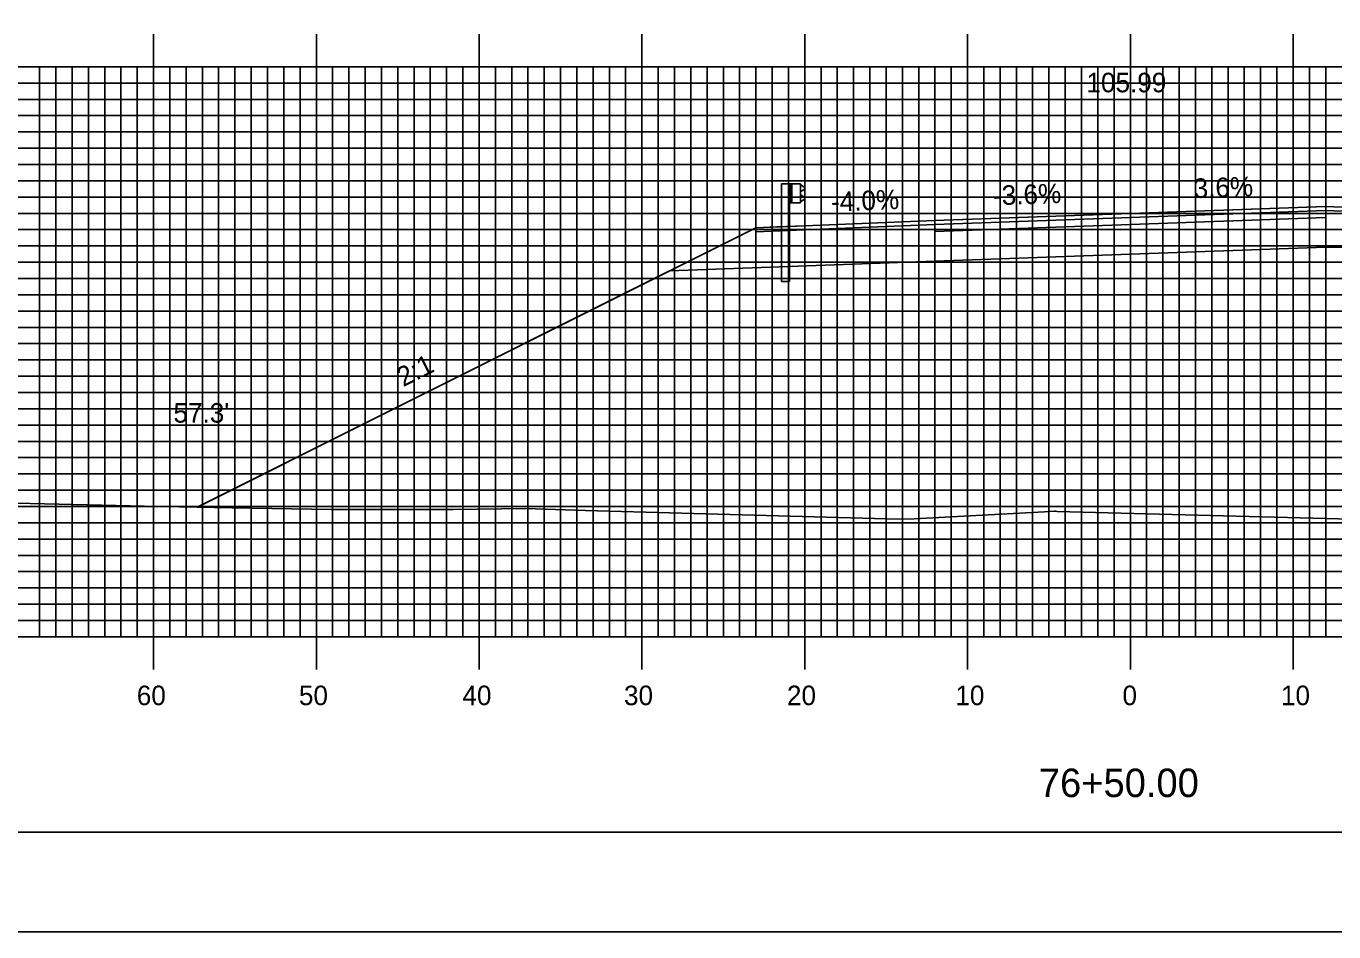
# Model space of a CAD drawing. Extents: x 1761791 to 1762134, y 442591 to 442811.
# Drawn here: x 1761888.9 to 1761969.3, y 442590.5 to 442646.2 of the extents above; entities that cross this region are included whole.
import ezdxf

# ---------------------------------------------------------------- set-up
doc = ezdxf.new("R2010")
doc.units = 0
for name, color, linetype in [('ANNOTATION', 7, 'Continuous'), ('BORDER', 7, 'Continuous'), ('D_Guardrail_Beam_Lt', 7, 'Continuous'), ('D_Roadway_Centerline', 7, 'Continuous'), ('D_Roadway_Centerline_Text', 7, 'Continuous'), ('D_Roadway_Edge_Shoulder', 7, 'Continuous'), ('D_Roadway_Edge_TW', 7, 'Continuous'), ('D_Roadway_Pavement', 7, 'Continuous'), ('D_Roadway_SlopeLines', 7, 'Continuous'), ('D_Roadway_SubGrade', 7, 'Continuous'), ('D_Text_Standard', 7, 'Continuous'), ('H_V ANNOTATION', 7, 'Continuous'), ('MAJOR', 7, 'Continuous'), ('MINOR', 7, 'Continuous'), ('PLOT BOUNDARY', 7, 'Continuous'), ('S_Roadway_Centerline', 7, 'Continuous')]:
    doc.layers.add(name, color=color, linetype=linetype)

msp = doc.modelspace()

# ---------------------------------------------------------------- linework, layer by layer
at = {"layer": 'BORDER'}
msp.add_lwpolyline([(1761807.153, 442596.665), (1762127.153, 442596.665), (1762127.153, 442806.665), (1761807.153, 442806.665)], close=True, dxfattribs=at)
at = {"layer": 'D_Guardrail_Beam_Lt'}
for p, q in [((1761935.324, 442636.487), (1761935.324, 442630.487)), ((1761935.795, 442636.487), (1761935.324, 442636.487)), ((1761936.483, 442636.487), (1761935.795, 442636.487)), ((1761935.795, 442636.487), (1761935.795, 442635.32)), ((1761935.858, 442636.487), (1761935.858, 442635.32)), ((1761935.962, 442636.487), (1761935.962, 442635.32)), ((1761936.483, 442635.32), (1761936.483, 442636.487)), ((1761936.483, 442636.403), (1761936.557, 442636.389)), ((1761936.716, 442636.139), (1761936.521, 442636.003)), ((1761936.573, 442636.382), (1761936.716, 442636.282)), ((1761936.557, 442635.418), (1761936.483, 442635.403)), ((1761936.487, 442635.938), (1761936.487, 442635.868)), ((1761936.521, 442635.804), (1761936.716, 442635.668)), ((1761936.716, 442635.524), (1761936.573, 442635.424)), ((1761935.795, 442635.32), (1761936.483, 442635.32)), ((1761935.816, 442630.487), (1761935.816, 442635.32)), ((1761935.816, 442630.487), (1761935.324, 442630.487))]:
    msp.add_line(p, q, dxfattribs=at)
for centre, major_axis, start_param, end_param in [((1761936.549, 442636.348), (0.0417, 0), 0.959931, 1.376053), ((1761936.666, 442636.21), (0.0877, 0), 5.323254, 7.243116), ((1761936.566, 442635.938), (-0.0789, 0), 5.323254, 6.283185), ((1761936.566, 442635.868), (-0.0789, 0), 6.283185, 7.243116), ((1761936.549, 442635.458), (0.0417, 0), 4.907132, 5.323254), ((1761936.666, 442635.596), (0.0877, 0), 5.323254, 7.243116)]:
    msp.add_ellipse(centre, major_axis=major_axis, ratio=0.995501, start_param=start_param, end_param=end_param, dxfattribs=at)
at = {"layer": 'D_Roadway_Centerline'}
msp.add_lwpolyline([(1761899.435, 442616.624), (1761899.444, 442616.629), (1761910.406, 442622.109), (1761928.445, 442631.129), (1761928.46, 442631.136), (1761933.753, 442633.783), (1761935.042, 442633.835), (1761936.754, 442633.903), (1761944.753, 442634.223), (1761956.75, 442634.655), (1761956.753, 442634.655), (1761968.75, 442635.087), (1761968.753, 442635.087), (1761968.755, 442635.087), (1761976.753, 442634.767), (1761976.754, 442634.767), (1761979.753, 442634.647), (1761984.501, 442632.273), (1761984.503, 442632.272), (1762000.789, 442624.129), (1762017.753, 442615.647)], dxfattribs=at)
at = {"layer": 'D_Roadway_Edge_Shoulder'}
for points in [[(1761968.753, 442635.087), (1761976.753, 442634.767), (1761976.753, 442634.767), (1761979.753, 442634.647), (1761979.753, 442634.397), (1761968.753, 442634.837)], [(1761944.753, 442634.223), (1761936.754, 442633.903), (1761936.754, 442633.903), (1761933.753, 442633.783), (1761933.753, 442633.533), (1761944.753, 442633.973)]]:
    msp.add_lwpolyline(points, close=True, dxfattribs=at)
at = {"layer": 'D_Roadway_Edge_TW'}
msp.add_lwpolyline([(1761944.753, 442633.973), (1761944.753, 442634.223), (1761956.753, 442634.655), (1761968.753, 442635.087), (1761968.753, 442634.837), (1761956.753, 442634.405)], close=True, dxfattribs=at)
at = {"layer": 'D_Roadway_Pavement'}
msp.add_lwpolyline([(1761944.753, 442633.556), (1761944.753, 442633.973), (1761956.753, 442634.405), (1761968.753, 442634.837), (1761968.753, 442634.42), (1761956.753, 442633.988)], close=True, dxfattribs=at)
for points in [[(1761968.753, 442634.837), (1761968.753, 442634.42)], [(1761944.753, 442633.973), (1761944.753, 442633.556)]]:
    msp.add_lwpolyline(points, dxfattribs=at)
at = {"layer": 'D_Roadway_SlopeLines'}
msp.add_lwpolyline([(1761933.753, 442633.783), (1761899.435, 442616.624)], dxfattribs=at)
at = {"layer": 'D_Roadway_SubGrade'}
for points in [[(1761944.753, 442631.723), (1761944.753, 442633.973), (1761944.753, 442633.556), (1761956.753, 442633.988), (1761968.753, 442634.42), (1761968.753, 442634.837), (1761968.753, 442632.587), (1761956.753, 442632.155)], [(1761968.753, 442634.42), (1761968.753, 442634.837), (1761979.753, 442634.397), (1761979.753, 442634.647), (1761984.503, 442632.272), (1761968.753, 442632.587)], [(1761944.753, 442633.556), (1761944.753, 442633.973), (1761933.753, 442633.533), (1761933.753, 442633.783), (1761928.46, 442631.136), (1761944.753, 442631.723)]]:
    msp.add_lwpolyline(points, close=True, dxfattribs=at)
at = {"layer": 'MAJOR'}
for p, q in [((1761896.753, 442645.669), (1761896.753, 442643.665)), ((1761906.753, 442645.669), (1761906.753, 442643.665)), ((1761916.753, 442645.669), (1761916.753, 442643.665)), ((1761926.753, 442645.669), (1761926.753, 442643.665)), ((1761936.753, 442645.669), (1761936.753, 442643.665)), ((1761946.753, 442645.669), (1761946.753, 442643.665)), ((1761956.753, 442645.669), (1761956.753, 442643.665)), ((1761966.753, 442645.669), (1761966.753, 442643.665)), ((1761816.753, 442643.665), (1762096.753, 442643.665)), ((1761816.753, 442643.665), (1762096.753, 442643.665)), ((1761896.753, 442608.665), (1761896.753, 442643.665)), ((1761906.753, 442608.665), (1761906.753, 442643.665)), ((1761916.753, 442608.665), (1761916.753, 442643.665)), ((1761926.753, 442608.665), (1761926.753, 442643.665)), ((1761936.753, 442608.665), (1761936.753, 442643.665)), ((1761946.753, 442608.665), (1761946.753, 442643.665)), ((1761956.753, 442608.665), (1761956.753, 442643.665)), ((1761966.753, 442608.665), (1761966.753, 442643.665)), ((1761816.753, 442638.665), (1762096.753, 442638.665)), ((1761816.753, 442633.665), (1762096.753, 442633.665)), ((1761816.753, 442628.665), (1762096.753, 442628.665)), ((1761816.753, 442623.665), (1762096.753, 442623.665)), ((1761816.753, 442618.665), (1762096.753, 442618.665)), ((1761816.753, 442613.665), (1762096.753, 442613.665)), ((1761816.753, 442608.665), (1762096.753, 442608.665)), ((1761816.753, 442608.665), (1762096.753, 442608.665)), ((1761896.753, 442606.661), (1761896.753, 442608.665)), ((1761906.753, 442606.661), (1761906.753, 442608.665)), ((1761916.753, 442606.661), (1761916.753, 442608.665)), ((1761926.753, 442606.661), (1761926.753, 442608.665)), ((1761936.753, 442606.661), (1761936.753, 442608.665)), ((1761946.753, 442606.661), (1761946.753, 442608.665)), ((1761956.753, 442606.661), (1761956.753, 442608.665)), ((1761966.753, 442606.661), (1761966.753, 442608.665))]:
    msp.add_line(p, q, dxfattribs=at)
at = {"layer": 'MINOR'}
for p, q in [((1761889.753, 442608.665), (1761889.753, 442643.665)), ((1761890.753, 442608.665), (1761890.753, 442643.665)), ((1761891.753, 442608.665), (1761891.753, 442643.665)), ((1761892.753, 442608.665), (1761892.753, 442643.665)), ((1761893.753, 442608.665), (1761893.753, 442643.665)), ((1761894.753, 442608.665), (1761894.753, 442643.665)), ((1761895.753, 442608.665), (1761895.753, 442643.665)), ((1761897.753, 442608.665), (1761897.753, 442643.665)), ((1761898.753, 442608.665), (1761898.753, 442643.665)), ((1761899.753, 442608.665), (1761899.753, 442643.665)), ((1761900.753, 442608.665), (1761900.753, 442643.665)), ((1761901.753, 442608.665), (1761901.753, 442643.665)), ((1761902.753, 442608.665), (1761902.753, 442643.665)), ((1761903.753, 442608.665), (1761903.753, 442643.665)), ((1761904.753, 442608.665), (1761904.753, 442643.665)), ((1761905.753, 442608.665), (1761905.753, 442643.665)), ((1761907.753, 442608.665), (1761907.753, 442643.665)), ((1761908.753, 442608.665), (1761908.753, 442643.665)), ((1761909.753, 442608.665), (1761909.753, 442643.665)), ((1761910.753, 442608.665), (1761910.753, 442643.665)), ((1761911.753, 442608.665), (1761911.753, 442643.665)), ((1761912.753, 442608.665), (1761912.753, 442643.665)), ((1761913.753, 442608.665), (1761913.753, 442643.665)), ((1761914.753, 442608.665), (1761914.753, 442643.665)), ((1761915.753, 442608.665), (1761915.753, 442643.665)), ((1761917.753, 442608.665), (1761917.753, 442643.665)), ((1761918.753, 442608.665), (1761918.753, 442643.665)), ((1761919.753, 442608.665), (1761919.753, 442643.665)), ((1761920.753, 442608.665), (1761920.753, 442643.665)), ((1761921.753, 442608.665), (1761921.753, 442643.665)), ((1761922.753, 442608.665), (1761922.753, 442643.665)), ((1761923.753, 442608.665), (1761923.753, 442643.665)), ((1761924.753, 442608.665), (1761924.753, 442643.665)), ((1761925.753, 442608.665), (1761925.753, 442643.665)), ((1761927.753, 442608.665), (1761927.753, 442643.665)), ((1761928.753, 442608.665), (1761928.753, 442643.665)), ((1761929.753, 442608.665), (1761929.753, 442643.665)), ((1761930.753, 442608.665), (1761930.753, 442643.665)), ((1761931.753, 442608.665), (1761931.753, 442643.665)), ((1761932.753, 442608.665), (1761932.753, 442643.665)), ((1761933.753, 442608.665), (1761933.753, 442643.665)), ((1761934.753, 442608.665), (1761934.753, 442643.665)), ((1761935.753, 442608.665), (1761935.753, 442643.665)), ((1761937.753, 442608.665), (1761937.753, 442643.665)), ((1761938.753, 442608.665), (1761938.753, 442643.665)), ((1761939.753, 442608.665), (1761939.753, 442643.665)), ((1761940.753, 442608.665), (1761940.753, 442643.665)), ((1761941.753, 442608.665), (1761941.753, 442643.665)), ((1761942.753, 442608.665), (1761942.753, 442643.665)), ((1761943.753, 442608.665), (1761943.753, 442643.665)), ((1761944.753, 442608.665), (1761944.753, 442643.665)), ((1761945.753, 442608.665), (1761945.753, 442643.665)), ((1761947.753, 442608.665), (1761947.753, 442643.665)), ((1761948.753, 442608.665), (1761948.753, 442643.665)), ((1761949.753, 442608.665), (1761949.753, 442643.665)), ((1761950.753, 442608.665), (1761950.753, 442643.665)), ((1761951.753, 442608.665), (1761951.753, 442643.665)), ((1761952.753, 442608.665), (1761952.753, 442643.665)), ((1761953.753, 442608.665), (1761953.753, 442643.665)), ((1761954.753, 442608.665), (1761954.753, 442643.665)), ((1761955.753, 442608.665), (1761955.753, 442643.665)), ((1761957.753, 442608.665), (1761957.753, 442643.665)), ((1761958.753, 442608.665), (1761958.753, 442643.665)), ((1761959.753, 442608.665), (1761959.753, 442643.665)), ((1761960.753, 442608.665), (1761960.753, 442643.665)), ((1761961.753, 442608.665), (1761961.753, 442643.665)), ((1761962.753, 442608.665), (1761962.753, 442643.665)), ((1761963.753, 442608.665), (1761963.753, 442643.665)), ((1761964.753, 442608.665), (1761964.753, 442643.665)), ((1761965.753, 442608.665), (1761965.753, 442643.665)), ((1761967.753, 442608.665), (1761967.753, 442643.665)), ((1761968.753, 442608.665), (1761968.753, 442643.665)), ((1761816.753, 442642.665), (1762096.753, 442642.665)), ((1761816.753, 442641.665), (1762096.753, 442641.665)), ((1761816.753, 442640.665), (1762096.753, 442640.665)), ((1761816.753, 442639.665), (1762096.753, 442639.665)), ((1761816.753, 442637.665), (1762096.753, 442637.665)), ((1761816.753, 442636.665), (1762096.753, 442636.665)), ((1761816.753, 442635.665), (1762096.753, 442635.665)), ((1761816.753, 442634.665), (1762096.753, 442634.665)), ((1761816.753, 442632.665), (1762096.753, 442632.665)), ((1761816.753, 442631.665), (1762096.753, 442631.665)), ((1761816.753, 442630.665), (1762096.753, 442630.665)), ((1761816.753, 442629.665), (1762096.753, 442629.665)), ((1761816.753, 442627.665), (1762096.753, 442627.665)), ((1761816.753, 442626.665), (1762096.753, 442626.665)), ((1761816.753, 442625.665), (1762096.753, 442625.665)), ((1761816.753, 442624.665), (1762096.753, 442624.665)), ((1761816.753, 442622.665), (1762096.753, 442622.665)), ((1761816.753, 442621.665), (1762096.753, 442621.665)), ((1761816.753, 442620.665), (1762096.753, 442620.665)), ((1761816.753, 442619.665), (1762096.753, 442619.665)), ((1761816.753, 442617.665), (1762096.753, 442617.665)), ((1761816.753, 442616.665), (1762096.753, 442616.665)), ((1761816.753, 442615.665), (1762096.753, 442615.665)), ((1761816.753, 442614.665), (1762096.753, 442614.665)), ((1761816.753, 442612.665), (1762096.753, 442612.665)), ((1761816.753, 442611.665), (1762096.753, 442611.665)), ((1761816.753, 442610.665), (1762096.753, 442610.665)), ((1761816.753, 442609.665), (1762096.753, 442609.665))]:
    msp.add_line(p, q, dxfattribs=at)
at = {"layer": 'PLOT BOUNDARY'}
msp.add_lwpolyline([(1761790.966, 442590.547), (1762130.966, 442590.547), (1762130.966, 442810.547), (1761790.966, 442810.547)], close=True, dxfattribs=at)
at = {"layer": 'S_Roadway_Centerline'}
msp.add_lwpolyline([(1761888.296, 442616.865), (1761896.19, 442616.686), (1761901.589, 442616.583), (1761907.672, 442616.485), (1761915.167, 442616.472), (1761919.602, 442616.533), (1761923.286, 442616.424), (1761941.048, 442615.935), (1761942.423, 442615.888), (1761943.472, 442615.914), (1761951.474, 442616.337), (1761952.072, 442616.37), (1761952.155, 442616.37), (1761952.254, 442616.367), (1761973.477, 442615.809), (1761975.588, 442615.788), (1761978.129, 442615.735), (1761987.369, 442615.8), (1761994.746, 442615.813), (1761999.513, 442615.98), (1762005.007, 442615.76), (1762014.874, 442615.602), (1762021.594, 442615.707)], dxfattribs=at)

# ---------------------------------------------------------------- texts
at = {"layer": 'ANNOTATION'}
for s, rotation, p in [('-3.6%', 2.06162, (1761948.338, 442635.154)), ('3.6%', 2.06186, (1761960.659, 442635.597)), ('-4.0%', 2.29087, (1761938.385, 442634.77)), ('2:1', 26.56465, (1761912.09, 442623.987))]:
    msp.add_text(s, height=1.2, rotation=rotation, dxfattribs=at).set_placement(p)
at = {"layer": 'D_Roadway_Centerline'}
for s, p in [('C', (1761956.748, 442634.655)), ('L', (1761956.753, 442634.648))]:
    msp.add_text(s, height=0.0146, dxfattribs=at).set_placement(p)
at = {"layer": 'D_Roadway_Centerline_Text'}
msp.add_text('105.99', height=1.2, dxfattribs=at).set_placement((1761954.056, 442642.098))
at = {"layer": 'D_Text_Standard'}
msp.add_text("57.3'", height=1.2, dxfattribs=at).set_placement((1761897.977, 442621.814))
at = {"layer": 'H_V ANNOTATION'}
for s, height, p in [('60', 1.2, (1761895.725, 442604.465)), ('50', 1.2, (1761905.682, 442604.465)), ('40', 1.2, (1761915.725, 442604.465)), ('30', 1.2, (1761925.65, 442604.465)), ('20', 1.2, (1761935.661, 442604.465)), ('10', 1.2, (1761946.004, 442604.465)), ('0', 1.2, (1761956.271, 442604.465)), ('10', 1.2, (1761966.004, 442604.465)), ('76+50.00', 1.75, (1761951.135, 442598.821))]:
    msp.add_text(s, height=height, dxfattribs=at).set_placement(p)

doc.saveas('drawing.dxf')
